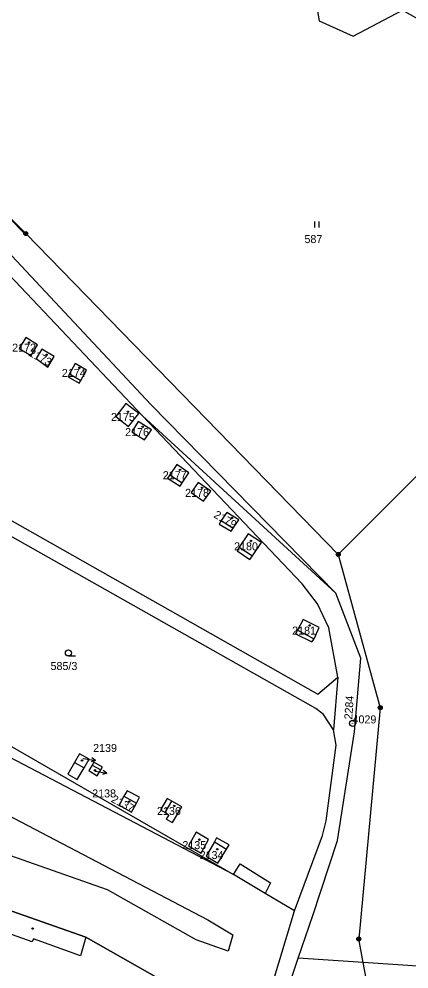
# Model space of a CAD drawing. Extents: x -555757 to -553364, y -1100723 to -1096439.
# Drawn here: x -553863.9 to -553766.6, y -1099265.3 to -1099027.9 of the extents above; entities that cross this region are included whole.
import ezdxf

# ---------------------------------------------------------------- set-up
doc = ezdxf.new("R2010")
doc.units = 0
for name, color, linetype in [('00_NÁVRH - 0.35 mm', 7, 'Continuous'), ('01_HLADINA', 7, 'Continuous'), ('05_SÍTĚ - vedení VN - nadzemní', 7, 'Continuous'), ('BUDOVY', 7, 'Continuous'), ('C$SLO$PARCELY', 7, 'Continuous'), ('CISLO_PBPP', 7, 'Continuous'), ('HRANICE$PARCELY', 7, 'Continuous'), ('HRANICE$POROSTU', 7, 'Continuous'), ('HRANICE_PARCEL', 7, 'Continuous'), ('PLOTY', 7, 'Continuous'), ('SLOUPY', 7, 'Continuous'), ('SLUCKOV$$C$RA', 7, 'Continuous'), ('STROMY', 7, 'Continuous'), ('VCHOD', 7, 'Continuous'), ('ZNA$KY$KULTUR', 7, 'Continuous')]:
    doc.layers.add(name, color=color, linetype=linetype)

# ---------------------------------------------------------------- blocks, each defined once
blk = doc.blocks.new('1$01')
at = {"layer": 'SLOUPY'}
for radius in [0.75, 0.032]:
    blk.add_circle((0, 0), radius, dxfattribs=at)
blk = doc.blocks.new('4$02')
at = {"layer": 'SLOUPY'}
blk.add_circle((0, 0), 0.175, dxfattribs=at)
blk = doc.blocks.new('1029')
at = {"layer": 'PLOTY'}
for p, q in [((0, 0), (2.964, -0.468)), ((2.964, -0.468), (2.052, 0.182)), ((2.964, -0.468), (1.897, -0.807))]:
    blk.add_line(p, q, dxfattribs=at)
blk = doc.blocks.new('3$06')
at = {"layer": 'SLOUPY'}
for p, q in [((-0.517, 0.235), (-0.517, 1.735)), ((0.517, 0.235), (0.517, 1.735))]:
    blk.add_line(p, q, dxfattribs=at)
blk = doc.blocks.new('3$04')
at = {"layer": 'ZNA$KY$KULTUR'}
blk.add_line((0.01, 0), (1.76, 0), dxfattribs=at)
blk.add_circle((0.01, 0.75), 0.75, dxfattribs=at)
blk = doc.blocks.new('6$01')
at = {"layer": 'SLOUPY'}
for radius in [0.5, 0.3, 0.15]:
    blk.add_circle((0, 0), radius, dxfattribs=at)

msp = doc.modelspace()

# ---------------------------------------------------------------- linework, layer by layer
at = {"layer": '00_NÁVRH - 0.35 mm'}
msp.add_open_spline([(-553794.11, -1099299.31), (-553795.3, -1099298.08), (-553795.88, -1099297.7), (-553798.01, -1099296.38), (-553798.65, -1099296.01), (-553799.06, -1099295.87), (-553800.01, -1099295.63), (-553800.97, -1099295.43), (-553803.92, -1099294.98), (-553807.94, -1099294.4), (-553820.01, -1099292.71), (-553824.22, -1099292.09), (-553827.54, -1099291.56), (-553834.29, -1099290.18), (-553840, -1099289.07), (-553843.61, -1099288.31), (-553846.03, -1099287.85), (-553848, -1099287.45), (-553849.39, -1099287.28), (-553865.94, -1099285.25), (-553871.05, -1099284.8), (-553873.86, -1099284.51), (-553874.4, -1099284.43), (-553876.78, -1099283.97), (-553879.06, -1099283.33), (-553880.05, -1099283.03), (-553881.09, -1099282.39), (-553882.19, -1099281.75), (-553883.23, -1099281.08), (-553884.33, -1099279.97), (-553885.55, -1099278.71), (-553889.78, -1099274.4), (-553901.55, -1099262.43), (-553911.97, -1099251.72), (-553924.19, -1099239.3), (-553934.53, -1099228.74), (-553940.93, -1099222.27), (-553947.07, -1099216.54), (-553953.84, -1099210.49), (-553956.73, -1099207.94), (-553957.05, -1099207.63), (-553964.75, -1099199.61), (-553968.13, -1099195.98), (-553972.84, -1099191.05), (-553973.28, -1099190.44), (-553973.66, -1099189.74), (-553976.66, -1099181.56), (-553981.28, -1099169.19), (-553982.8, -1099164.02), (-553982.96, -1099163.18), (-553982.84, -1099162.2), (-553982.62, -1099160.64), (-553981.35, -1099154.45), (-553980.69, -1099150.99), (-553979.68, -1099146.66), (-553979.44, -1099145.68), (-553978.92, -1099144.07), (-553976.62, -1099137.96), (-553971.5, -1099124.44), (-553956.51, -1099083), (-553948.35, -1099063.11), (-553947.15, -1099060.17), (-553946.29, -1099057.43), (-553943.53, -1099049.31), (-553939.7, -1099037.85), (-553934.37, -1099021.96), (-553930.78, -1099011.15), (-553926.74, -1098998.79), (-553924.69, -1098992.82), (-553921.26, -1098983.98), (-553917.56, -1098974.67), (-553914.06, -1098965.56), (-553908.69, -1098951.91), (-553901.82, -1098934.8), (-553901.39, -1098933.67), (-553901.1, -1098932.55), (-553900.65, -1098929.57), (-553899.92, -1098923.6), (-553898.96, -1098915.48), (-553898.39, -1098910.69), (-553898.13, -1098908.4), (-553898.22, -1098907.18), (-553898.46, -1098905.43), (-553899.12, -1098901.51), (-553900.51, -1098893.56), (-553900.64, -1098892.89), (-553900.54, -1098892.33), (-553900.23, -1098891.41), (-553899.45, -1098889.27), (-553897.42, -1098883.77), (-553893.02, -1098871.92), (-553886.93, -1098855.68), (-553885.61, -1098852.2), (-553884.63, -1098849.66), (-553884.11, -1098848.15), (-553883.86, -1098847.39), (-553883.79, -1098847), (-553883.77, -1098846.59), (-553883.8, -1098846.17), (-553883.86, -1098845.82), (-553884.32, -1098844.25), (-553887.68, -1098834.27), (-553890.61, -1098825.19), (-553891.02, -1098823.53), (-553891.07, -1098823.12), (-553891, -1098822.7), (-553890.8, -1098821.71), (-553890.2, -1098818.82), (-553888, -1098807.3), (-553885.79, -1098795.25), (-553885.36, -1098792.93), (-553885.23, -1098792.17), (-553885.15, -1098791.71), (-553885.15, -1098791.3), (-553885.15, -1098791.01), (-553885.22, -1098790.61), (-553886.5, -1098784.84), (-553888.27, -1098776.48), (-553889.52, -1098771.37), (-553889.7, -1098770.49), (-553889.76, -1098769.24), (-553890.01, -1098761.77), (-553890.33, -1098747.9), (-553890.42, -1098743.46), (-553890.42, -1098742.11), (-553890.41, -1098741.34), (-553890.23, -1098740.64), (-553887.44, -1098731.8), (-553883.47, -1098718.83), (-553877.88, -1098700.91), (-553873.65, -1098687.07), (-553869.07, -1098673.81), (-553863.43, -1098657.95), (-553859.62, -1098647.38), (-553854.52, -1098632.99), (-553853.78, -1098630.91), (-553852.9, -1098628.21), (-553851.15, -1098622.78), (-553848.21, -1098613.65), (-553844.19, -1098601.12), (-553841.04, -1098590.72), (-553837.17, -1098577.95), (-553835.01, -1098570.68), (-553833.04, -1098564.14), (-553830.71, -1098556.28), (-553828.59, -1098548.94), (-553827.55, -1098545.5), (-553827.33, -1098544.63), (-553827.11, -1098543.6), (-553826.94, -1098542.73), (-553826.69, -1098541.47), (-553826.53, -1098540.35), (-553825.37, -1098531.95), (-553823.55, -1098519.22), (-553822.41, -1098510.95), (-553821.27, -1098503.56), (-553820.36, -1098496.72), (-553819.26, -1098489.11), (-553818.91, -1098486.04), (-553818.85, -1098485.53), (-553818.85, -1098485.16), (-553818.85, -1098484.16), (-553818.79, -1098477.89), (-553818.64, -1098467.21), (-553818.46, -1098454.7), (-553818.1, -1098433.16), (-553817.83, -1098416.02), (-553817.76, -1098409.13), (-553817.72, -1098406.97), (-553817.48, -1098400.26), (-553817.11, -1098388.41), (-553816.88, -1098378.57), (-553816.92, -1098376.34), (-553817.08, -1098375.51), (-553817.65, -1098372.67), (-553823.7, -1098343.15), (-553824.05, -1098341.6), (-553824.65, -1098340.01), (-553827.06, -1098334.58), (-553831.23, -1098324.89), (-553836.05, -1098314.24), (-553837.07, -1098312.26), (-553794.64, -1099298.64), (-553836.55, -1098313.25)], degree=3, dxfattribs=at)
at = {"layer": '01_HLADINA'}
for points in [[(-553886.71, -1099243.37), (-553871.98, -1099248.68), (-553847.28, -1099257.34), (-553825.17, -1099269.91), (-553809.2, -1099275.46), (-553802.76, -1099275.65), (-553800.95, -1099269.84), (-553795.19, -1099250.73), (-553802.54, -1099246.44), (-553810.39, -1099241.64), (-553878.65, -1099205.91), (-553912.19, -1099190.69), (-553924.01, -1099208.05), (-553918.09, -1099213.65), (-553886.71, -1099243.37)], [(-553904.82, -1099208.31), (-553884.35, -1099217.6), (-553816.8, -1099252.96), (-553810.58, -1099256.76), (-553811.8, -1099260.79), (-553819.78, -1099258.02), (-553841.87, -1099245.46), (-553867.62, -1099236.43), (-553879.74, -1099232.06), (-553904.82, -1099208.31)]]:
    msp.add_lwpolyline(points, dxfattribs=at)
at = {"layer": '05_SÍTĚ - vedení VN - nadzemní'}
msp.add_lwpolyline([(-553941.16, -1099001.05), (-553862.6, -1099081.53)], dxfattribs=at)
at = {"layer": 'HRANICE$PARCELY'}
for p, q in [((-553833.16, -1099127.04), (-553917.14, -1099038.14)), ((-553784.36, -1099192.38), (-553785.47, -1099205.55))]:
    msp.add_line(p, q, dxfattribs=at)
for points in [[(-553917.14, -1099038.14), (-553923.89, -1099030.97), (-553930.65, -1099032.58), (-553953.88, -1099096.97), (-553954.05, -1099100.45), (-553953.13, -1099103.77), (-553789.4, -1099196.56), (-553784.36, -1099192.38)], [(-553785.47, -1099205.55), (-553787.98, -1099201.67), (-553789.9, -1099200.15), (-553952.82, -1099108.08), (-553958.7, -1099110.01), (-553974.06, -1099151.74), (-553975.53, -1099163.25), (-553971.46, -1099180.55), (-553951.42, -1099202.73), (-553931.47, -1099218.69), (-553924.01, -1099208.05)], [(-553859.38, -1099109.29), (-553862.27, -1099107.48), (-553863.9, -1099110.22), (-553860.91, -1099112), (-553859.38, -1099109.29)], [(-553855.18, -1099112.19), (-553858.27, -1099110.43), (-553859.7, -1099112.72), (-553856.77, -1099114.86), (-553855.18, -1099112.19)], [(-553848.5, -1099118.21), (-553847.09, -1099115.63), (-553849.9, -1099113.95), (-553851.37, -1099116.52), (-553851.68, -1099117.34), (-553848.98, -1099118.91), (-553848.5, -1099118.21)], [(-553834.07, -1099126.45), (-553837.33, -1099123.97), (-553839.83, -1099127.18), (-553836.62, -1099129.68), (-553834.07, -1099126.45)], [(-553784.36, -1099192.38), (-553786.68, -1099180.03), (-553789.43, -1099174.06), (-553793.26, -1099169.01), (-553833.16, -1099127.04)], [(-553794.26, -1099262.52), (-553790.64, -1099251.86), (-553784.47, -1099233.17), (-553780.22, -1099205.99), (-553778.63, -1099187.62), (-553784.87, -1099171.36), (-553833.16, -1099127.04)], [(-553830.93, -1099130.59), (-553834.18, -1099128.51), (-553835.82, -1099131.07), (-553832.65, -1099133.08), (-553830.93, -1099130.59)], [(-553821.55, -1099141.32), (-553824.58, -1099139.23), (-553826.34, -1099141.78), (-553826.89, -1099142.59), (-553823.74, -1099144.63), (-553823.21, -1099143.83), (-553821.55, -1099141.32)], [(-553816.12, -1099145.9), (-553819.22, -1099143.7), (-553821.02, -1099146.24), (-553817.88, -1099148.41), (-553816.12, -1099145.9)], [(-553813.5, -1099153.2), (-553813.99, -1099154.11), (-553811.04, -1099155.89), (-553810.49, -1099155.08), (-553809.08, -1099153), (-553812.11, -1099151.18), (-553813.5, -1099153.2)], [(-553806.78, -1099156.5), (-553809, -1099159.84), (-553809.55, -1099160.79), (-553806.35, -1099162.93), (-553805.72, -1099162.01), (-553803.46, -1099158.73), (-553806.78, -1099156.5)], [(-553793.08, -1099177.9), (-553794.45, -1099180.6), (-553794.92, -1099181.53), (-553790.85, -1099183.53), (-553790.33, -1099182.76), (-553789.03, -1099179.95), (-553793.08, -1099177.9)], [(-553912.19, -1099190.69), (-553908.36, -1099185.19), (-553810.39, -1099241.64)], [(-553810.39, -1099241.64), (-553878.65, -1099205.91), (-553912.19, -1099190.69)], [(-553795.19, -1099250.73), (-553788.2, -1099231.92), (-553787.28, -1099228.27), (-553784.83, -1099209.34), (-553785.47, -1099205.55)], [(-553846.42, -1099212.85), (-553848.83, -1099211.49), (-553850.07, -1099213.64), (-553847.71, -1099215), (-553846.42, -1099212.85)], [(-553843.13, -1099214.86), (-553845.3, -1099213.61), (-553845.72, -1099214.3), (-553846.53, -1099215.7), (-553844.41, -1099217.03), (-553843.56, -1099215.52), (-553843.13, -1099214.86)], [(-553835.87, -1099226.05), (-553834.65, -1099223.83), (-553833.92, -1099222.36), (-553836.96, -1099220.78), (-553837.78, -1099222.1), (-553839, -1099224.37), (-553835.87, -1099226.05)], [(-553826.58, -1099226.71), (-553827.24, -1099227.82), (-553825.62, -1099228.66), (-553823.34, -1099224.73), (-553825.84, -1099223.33), (-553827.01, -1099222.68), (-553828.65, -1099225.52), (-553827.48, -1099226.2), (-553826.58, -1099226.71)], [(-553821.68, -1099234.52), (-553818.51, -1099236.32), (-553816.64, -1099232.88), (-553819.74, -1099231.1), (-553821.68, -1099234.52)], [(-553811.54, -1099234.28), (-553814.66, -1099232.5), (-553815.19, -1099233.5), (-553817.29, -1099237.05), (-553814.3, -1099238.83), (-553812.19, -1099235.29), (-553811.54, -1099234.28)], [(-553795.19, -1099250.73), (-553802.54, -1099246.44), (-553810.39, -1099241.64)], [(-553825.17, -1099269.91), (-553847.28, -1099257.34), (-553871.98, -1099248.68), (-553886.71, -1099243.37), (-553889.28, -1099242.44)], [(-553802.76, -1099275.65), (-553800.95, -1099269.84), (-553795.19, -1099250.73)], [(-553793.99, -1099282.92), (-553797.23, -1099277.96), (-553797.39, -1099271.76), (-553794.26, -1099262.52)], [(-553762.05, -1099264.73), (-553778.08, -1099263.63), (-553794.26, -1099262.52)]]:
    msp.add_lwpolyline(points, dxfattribs=at)
at = {"layer": 'HRANICE_PARCEL'}
msp.add_lwpolyline([(-553809.06, -1098956.84), (-553815.63, -1098964.9), (-553814.54, -1098978.25), (-553820.36, -1098989.33), (-553819.57, -1099006.07), (-553812.42, -1099008.81), (-553797.63, -1099006.46), (-553791.37, -1099014.79), (-553789.02, -1099028.4), (-553780.59, -1099032.22), (-553768.26, -1099025.71), (-553754.32, -1099033.57)], dxfattribs=at)
msp.add_lwpolyline([(-553809.06, -1098956.84), (-553815.63, -1098964.9), (-553814.54, -1098978.25), (-553820.36, -1098989.33), (-553819.57, -1099006.07), (-553812.42, -1099008.81), (-553797.63, -1099006.46), (-553791.37, -1099014.79), (-553789.02, -1099028.4), (-553780.59, -1099032.22), (-553768.26, -1099025.71), (-553754.32, -1099033.57)], dxfattribs=at)
at = {"layer": 'PLOTY'}
for p, q in [((-553847.9, -1099212.81), (-553847.83, -1099212.71)), ((-553844.98, -1099215.83), (-553844.98, -1099215.84))]:
    msp.add_line(p, q, dxfattribs=at)
at = {"layer": 'SLUCKOV$$C$RA'}
for p, q in [((-553831.07, -1099124.19), (-553916.09, -1099033.21)), ((-553851.37, -1099116.52), (-553848.5, -1099118.21)), ((-553784.87, -1099171.36), (-553831.07, -1099124.19)), ((-553826.34, -1099141.78), (-553823.21, -1099143.83)), ((-553813.5, -1099153.2), (-553810.49, -1099155.08)), ((-553809, -1099159.84), (-553805.72, -1099162.01)), ((-553794.45, -1099180.6), (-553790.33, -1099182.76)), ((-553850.07, -1099213.64), (-553851.75, -1099216.55)), ((-553849.45, -1099217.88), (-553847.71, -1099215)), ((-553845.72, -1099214.3), (-553843.56, -1099215.52)), ((-553851.75, -1099216.55), (-553849.45, -1099217.88)), ((-553837.78, -1099222.1), (-553834.65, -1099223.83)), ((-553827.48, -1099226.2), (-553825.84, -1099223.33)), ((-553815.19, -1099233.5), (-553812.19, -1099235.29)), ((-553810.39, -1099241.64), (-553808.79, -1099239.03)), ((-553808.79, -1099239.03), (-553801.17, -1099243.71)), ((-553801.17, -1099243.71), (-553802.54, -1099246.44)), ((-553860.65, -1099258.5), (-553873.69, -1099253.9)), ((-553860.36, -1099257.77), (-553860.65, -1099258.5)), ((-553848.57, -1099261.96), (-553860.36, -1099257.77)), ((-553847.28, -1099257.34), (-553848.57, -1099261.96))]:
    msp.add_line(p, q, dxfattribs=at)
at = {"layer": 'VCHOD'}
for p, q in [((-553941.49, -1099001.8), (-553862.27, -1099081.5)), ((-553784.27, -1099161.69), (-553862.27, -1099081.5)), ((-553750.01, -1099127.25), (-553784.27, -1099161.69)), ((-553784.27, -1099161.69), (-553773.8, -1099199.99)), ((-553773.8, -1099199.99), (-553779.17, -1099257.76)), ((-553778.08, -1099263.63), (-553779.17, -1099257.76)), ((-553773.41, -1099288.69), (-553778.08, -1099263.63))]:
    msp.add_line(p, q, dxfattribs=at)

# ---------------------------------------------------------------- block references
at = {"layer": 'BUDOVY'}
for p in [(-553861.45, -1099108.76), (-553857.08, -1099111.79), (-553848.93, -1099115.08), (-553836.77, -1099126.03), (-553833.09, -1099129.79), (-553823.75, -1099140.57), (-553818.26, -1099145.04), (-553810.84, -1099152.55), (-553806.08, -1099158.3), (-553791.44, -1099179.41), (-553848.24, -1099213.18), (-553845.01, -1099215.63), (-553836.39, -1099223.42), (-553825.22, -1099224.53), (-553818.92, -1099232.96), (-553814.48, -1099235.34), (-553860.55, -1099255.15)]:
    msp.add_blockref('4$02', p, dxfattribs=at)
at = {"layer": 'HRANICE$POROSTU'}
msp.add_blockref('1$01', (-553780.73, -1099203.9), dxfattribs=at)
at = {"layer": 'PLOTY'}
for p in [(-553847.83, -1099212.71), (-553844.98, -1099215.84)]:
    msp.add_blockref('1029', p, dxfattribs=at)
at = {"layer": 'VCHOD'}
for p in [(-553862.27, -1099081.5), (-553784.27, -1099161.69), (-553773.8, -1099199.99), (-553779.17, -1099257.76)]:
    msp.add_blockref('6$01', p, dxfattribs=at)
at = {"layer": 'ZNA$KY$KULTUR'}
for name, p in [('3$06', (-553789.6, -1099080.2)), ('3$04', (-553851.64, -1099187.05))]:
    msp.add_blockref(name, p, dxfattribs=at)

# ---------------------------------------------------------------- texts
at = {"layer": 'C$SLO$PARCELY'}
for s, p in [('587', (-553792.72, -1099083.89)), ('2172', (-553865.66, -1099111.02)), ('2174', (-553853.26, -1099117.34)), ('2175', (-553841, -1099128.33)), ('2176', (-553837.48, -1099132.11)), ('2177', (-553828.08, -1099142.89)), ('2178', (-553822.51, -1099147.3)), ('2180', (-553810.28, -1099160.66)), ('2181', (-553795.79, -1099181.71)), ('585/3', (-553856.09, -1099190.56)), ('2139', (-553845.46, -1099211.04)), ('2138', (-553845.69, -1099222.4)), ('2136', (-553829.51, -1099226.78)), ('2135', (-553823.19, -1099235.32)), ('2134', (-553818.88, -1099237.8))]:
    msp.add_text(s, height=2, dxfattribs=at).set_placement(p)
for s, rotation, p in [('2173', 332, (-553861.74, -1099111.93)), ('2179', 330, (-553815.54, -1099152.32)), ('2284', 86, (-553780.81, -1099202.99)), ('2137', 332, (-553841.12, -1099223.43))]:
    msp.add_text(s, height=2, rotation=rotation, dxfattribs=at).set_placement(p)
at = {"layer": 'CISLO_PBPP'}
msp.add_text('4029', height=2, dxfattribs=at).set_placement((-553780.73, -1099203.9))
at = {"layer": 'STROMY'}
msp.add_text('239.27', height=0.1, dxfattribs=at).set_placement((-553781.01, -1099203.95))

doc.saveas('drawing.dxf')
